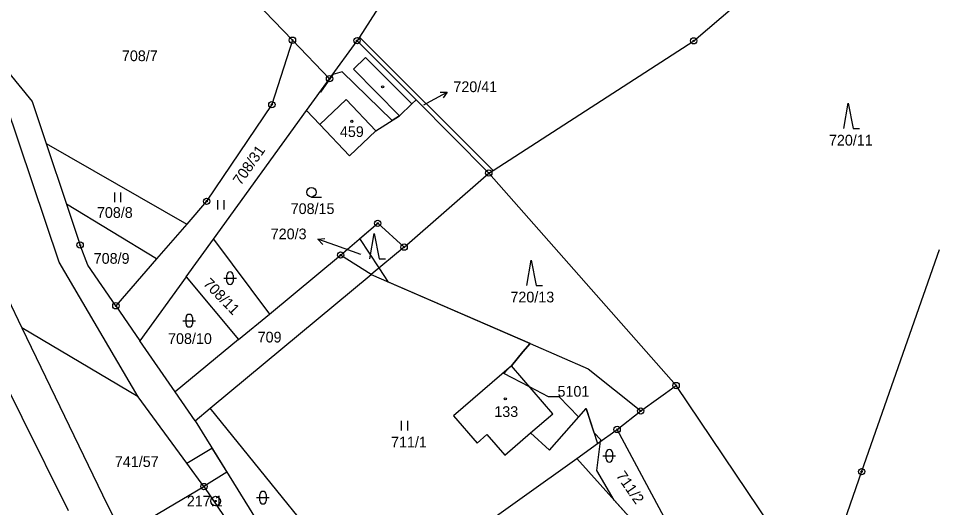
# Model space of a CAD drawing. Extents: x -439246 to -433691, y -1130252 to -1121148.
# Drawn here: x -436950.7 to -436805.1, y -1125491.1 to -1125413.5 of the extents above; entities that cross this region are included whole.
import ezdxf

# ---------------------------------------------------------------- set-up
doc = ezdxf.new("R2010")
doc.units = 0
for name, color, linetype in [('Vrstva 1', 7, 'Continuous'), ('Vrstva 16', 7, 'Continuous'), ('Vrstva 17', 7, 'Continuous'), ('Vrstva 18', 7, 'Continuous'), ('Vrstva 19', 7, 'Continuous'), ('Vrstva 24', 7, 'Continuous'), ('Vrstva 25', 7, 'Continuous'), ('Vrstva 3', 7, 'Continuous'), ('Vrstva 30', 7, 'Continuous'), ('Vrstva 37', 7, 'Continuous'), ('Vrstva 4', 7, 'Continuous'), ('Vrstva 52', 7, 'Continuous'), ('Vrstva 6', 7, 'Continuous')]:
    doc.layers.add(name, color=color, linetype=linetype)

msp = doc.modelspace()

# ---------------------------------------------------------------- linework, layer by layer
at = {"layer": 'Vrstva 1'}
for points in [[(-436927.94, -1125395.35), (-436907.12, -1125416.96)], [(-436843.38, -1125417.06), (-436817.3, -1125394.78)], [(-436887.02, -1125401.73), (-436896.49, -1125416.46)], [(-436965.4, -1125405.95), (-436948.45, -1125426.71)], [(-436907.12, -1125416.96), (-436910.39, -1125427.18), (-436920.75, -1125442.51)], [(-436907.12, -1125416.96), (-436901.23, -1125423.07)], [(-436901.23, -1125423.07), (-436896.86, -1125417.04)], [(-436896.49, -1125416.46), (-436896.86, -1125417.04)], [(-436896.86, -1125417.04), (-436887.49, -1125426.4)], [(-436875.23, -1125437.61), (-436843.38, -1125417.06)], [(-436904.89, -1125428.12), (-436901.23, -1125423.07)], [(-436888.17, -1125427.07), (-436887.49, -1125426.4)], [(-436887.49, -1125426.4), (-436875.93, -1125438.04)], [(-436944.18, -1125452.16), (-436952.63, -1125426.98)], [(-436948.45, -1125426.71), (-436946.24, -1125433.35)], [(-436888.17, -1125427.07), (-436890.09, -1125428.97)], [(-436919.68, -1125448.54), (-436904.89, -1125428.12)], [(-436902.75, -1125430.36), (-436904.89, -1125428.12)], [(-436893.88, -1125431.32), (-436890.09, -1125428.97)], [(-436902.75, -1125430.36), (-436898.04, -1125435.29)], [(-436898.04, -1125435.29), (-436893.88, -1125431.32)], [(-436946.24, -1125433.35), (-436923.9, -1125446.13)], [(-436946.24, -1125433.35), (-436943.03, -1125442.95)], [(-436889.38, -1125449.79), (-436875.93, -1125438.04)], [(-436875.93, -1125438.04), (-436875.23, -1125437.61)], [(-436846.17, -1125471.75), (-436875.93, -1125438.04)], [(-436928.71, -1125451.67), (-436943.03, -1125442.95)], [(-436943.03, -1125442.95), (-436940.85, -1125449.46)], [(-436920.75, -1125442.51), (-436923.9, -1125446.13)], [(-436923.9, -1125446.13), (-436928.71, -1125451.67)], [(-436899.47, -1125451.05), (-436893.57, -1125446.01)], [(-436893.57, -1125446.01), (-436889.38, -1125449.79)], [(-436939.63, -1125452.63), (-436940.85, -1125449.46)], [(-436924.02, -1125454.53), (-436919.68, -1125448.54)], [(-436919.68, -1125448.54), (-436910.79, -1125460.41)], [(-436910.79, -1125460.41), (-436899.47, -1125451.05)], [(-436894.61, -1125454.14), (-436899.47, -1125451.05)], [(-436889.38, -1125449.79), (-436894.61, -1125454.14)], [(-436804.38, -1125450.21), (-436816.7, -1125485.41)], [(-436931.61, -1125473.53), (-436944.18, -1125452.16)], [(-436935.17, -1125459.1), (-436939.63, -1125452.63)], [(-436928.71, -1125451.67), (-436935.17, -1125459.1)], [(-436924.02, -1125454.53), (-436931.35, -1125464.65)], [(-436924.02, -1125454.53), (-436915.7, -1125464.46)], [(-436920.18, -1125475.35), (-436894.61, -1125454.14)], [(-436894.61, -1125454.14), (-436869.38, -1125465.08)], [(-436952.37, -1125457.85), (-436950.1, -1125462.57)], [(-436935.17, -1125459.1), (-436931.35, -1125464.65)], [(-436915.7, -1125464.46), (-436910.79, -1125460.41)], [(-436942.68, -1125491.62), (-436957.49, -1125462.02)], [(-436931.61, -1125473.53), (-436950.1, -1125462.57)], [(-436950.1, -1125462.57), (-436936.58, -1125490.62)], [(-436925.75, -1125472.77), (-436931.35, -1125464.65)], [(-436915.7, -1125464.46), (-436925.75, -1125472.77)], [(-436869.38, -1125465.08), (-436870.54, -1125466.41), (-436872.33, -1125468.61)], [(-436869.38, -1125465.08), (-436860.12, -1125469.1)], [(-436872.33, -1125468.61), (-436881.53, -1125476.54), (-436877.79, -1125480.87), (-436876.22, -1125479.51), (-436873.36, -1125482.79), (-436869.29, -1125479.28)], [(-436869.29, -1125479.28), (-436865.78, -1125476.26), (-436872.33, -1125468.61)], [(-436860.12, -1125469.1), (-436851.79, -1125475.78)], [(-436922.59, -1125477.35), (-436925.75, -1125472.77)], [(-436851.79, -1125475.78), (-436846.17, -1125471.75)], [(-436823.62, -1125505.2), (-436846.17, -1125471.75)], [(-436923.89, -1125484.05), (-436931.61, -1125473.53)], [(-436922.59, -1125477.35), (-436920.18, -1125475.35)], [(-436894.71, -1125506.76), (-436920.18, -1125475.35)], [(-436866.29, -1125481.99), (-436860.48, -1125475.37)], [(-436860.48, -1125475.37), (-436858.64, -1125480.94)], [(-436855.54, -1125478.72), (-436851.79, -1125475.78)], [(-436922.59, -1125477.35), (-436901.39, -1125511.56)], [(-436858.64, -1125480.94), (-436855.54, -1125478.72)], [(-436844.53, -1125499.26), (-436855.54, -1125478.72)], [(-436866.29, -1125481.99), (-436869.29, -1125479.28)], [(-436861.96, -1125483.32), (-436858.64, -1125480.94)], [(-436921.18, -1125487.78), (-436923.89, -1125484.05)], [(-436878.93, -1125495.46), (-436861.96, -1125483.32)], [(-436846.62, -1125500.38), (-436861.96, -1125483.32)], [(-436816.7, -1125485.41), (-436823.62, -1125505.2)], [(-436933.11, -1125494.8), (-436921.18, -1125487.78)], [(-436921.18, -1125487.78), (-436906.49, -1125509.43)], [(-436936.58, -1125490.62), (-436934.13, -1125495.4)]]:
    msp.add_lwpolyline(points, dxfattribs=at)
at = {"layer": 'Vrstva 16'}
for p, q in [((-436885.18, -1125426.63), (-436882.55, -1125425.19)), ((-436900.24, -1125449.55), (-436903.07, -1125448.55))]:
    msp.add_line(p, q, dxfattribs=at)
for points in [[(-436883.66, -1125425.23), (-436882.55, -1125425.19), (-436883.18, -1125426.11)], [(-436886.24, -1125427.21), (-436885.18, -1125426.63)], [(-436902.29, -1125449.35), (-436903.07, -1125448.55), (-436901.96, -1125448.41)], [(-436896.28, -1125450.96), (-436900.24, -1125449.55)]]:
    msp.add_lwpolyline(points, dxfattribs=at)
at = {"layer": 'Vrstva 24'}
for centre, radius in [((-436907.12, -1125416.96), 0.5), ((-436907.12, -1125416.96), 0.1), ((-436896.86, -1125417.04), 0.5), ((-436896.86, -1125417.04), 0.1), ((-436843.38, -1125417.06), 0.5), ((-436843.38, -1125417.06), 0.1), ((-436901.23, -1125423.07), 0.5), ((-436901.23, -1125423.07), 0.1), ((-436910.39, -1125427.18), 0.5), ((-436910.39, -1125427.18), 0.1), ((-436875.93, -1125438.04), 0.5), ((-436875.93, -1125438.04), 0.1), ((-436920.75, -1125442.51), 0.5), ((-436920.75, -1125442.51), 0.1), ((-436893.57, -1125446.01), 0.5), ((-436893.57, -1125446.01), 0.1), ((-436940.85, -1125449.46), 0.5), ((-436940.85, -1125449.46), 0.1), ((-436889.38, -1125449.79), 0.5), ((-436889.38, -1125449.79), 0.1), ((-436899.47, -1125451.05), 0.5), ((-436899.47, -1125451.05), 0.1), ((-436935.17, -1125459.1), 0.5), ((-436935.17, -1125459.1), 0.1), ((-436846.17, -1125471.75), 0.5), ((-436846.17, -1125471.75), 0.1), ((-436851.79, -1125475.78), 0.5), ((-436851.79, -1125475.78), 0.1), ((-436855.54, -1125478.72), 0.5), ((-436855.54, -1125478.72), 0.1), ((-436816.7, -1125485.41), 0.5), ((-436816.7, -1125485.41), 0.1), ((-436921.18, -1125487.78), 0.5), ((-436921.18, -1125487.78), 0.1), ((-436919.32, -1125490.08), 0.75), ((-436919.32, -1125490.08), 0.1)]:
    msp.add_circle(centre, radius, dxfattribs=at)
at = {"layer": 'Vrstva 25'}
for p, q in [((-436935.36, -1125442.64), (-436935.36, -1125441.14)), ((-436934.36, -1125442.64), (-436934.36, -1125441.14)), ((-436918.95, -1125443.82), (-436918.95, -1125442.32)), ((-436917.95, -1125443.82), (-436917.95, -1125442.32)), ((-436904.1, -1125441.84), (-436902.5, -1125441.84)), ((-436918.03, -1125454.73), (-436916.03, -1125454.73)), ((-436917.53, -1125455.23), (-436917.53, -1125454.23)), ((-436916.53, -1125454.23), (-436916.53, -1125455.23)), ((-436924.02, -1125461.96), (-436924.02, -1125460.96)), ((-436923.02, -1125460.96), (-436923.02, -1125461.96)), ((-436924.52, -1125461.46), (-436922.52, -1125461.46)), ((-436889.78, -1125478.87), (-436889.78, -1125477.37)), ((-436888.78, -1125478.87), (-436888.78, -1125477.37)), ((-436857.79, -1125482.9), (-436855.79, -1125482.9)), ((-436857.29, -1125483.4), (-436857.29, -1125482.4)), ((-436856.29, -1125482.4), (-436856.29, -1125483.4)), ((-436912.31, -1125490.04), (-436912.31, -1125489.04)), ((-436911.31, -1125489.04), (-436911.31, -1125490.04)), ((-436912.81, -1125489.54), (-436910.81, -1125489.54))]:
    msp.add_line(p, q, dxfattribs=at)
for points in [[(-436819.52, -1125430.97), (-436818.82, -1125426.97), (-436818.02, -1125430.97), (-436817.02, -1125430.97)], [(-436894.83, -1125451.65), (-436894.13, -1125447.65), (-436893.33, -1125451.65), (-436892.33, -1125451.65)], [(-436869.9, -1125455.86), (-436869.2, -1125451.86), (-436868.4, -1125455.86), (-436867.4, -1125455.86)]]:
    msp.add_lwpolyline(points, dxfattribs=at)
for centre, radius in [((-436892.8, -1125424.36), 0.175), ((-436897.69, -1125429.83), 0.175), ((-436904.1, -1125441.09), 0.75), ((-436873.31, -1125473.86), 0.175)]:
    msp.add_circle(centre, radius, dxfattribs=at)
for centre, start, end in [((-436917.03, -1125454.23), 0, 180), ((-436917.03, -1125455.23), 180, 0), ((-436923.52, -1125460.96), 0, 180), ((-436923.52, -1125461.96), 180, 0), ((-436856.79, -1125482.4), 0, 180), ((-436856.79, -1125483.4), 180, 0), ((-436911.81, -1125489.04), 0, 180), ((-436911.81, -1125490.04), 180, 0)]:
    msp.add_arc(centre, 0.5, start, end, dxfattribs=at)
at = {"layer": 'Vrstva 3'}
for points in [[(-436902.75, -1125430.36), (-436898.59, -1125426.39)], [(-436898.59, -1125426.39), (-436893.88, -1125431.32)], [(-436902.75, -1125430.36), (-436898.04, -1125435.29)], [(-436898.04, -1125435.29), (-436893.88, -1125431.32)], [(-436872.33, -1125468.61), (-436881.53, -1125476.54), (-436877.79, -1125480.87), (-436876.22, -1125479.51), (-436873.36, -1125482.79), (-436869.29, -1125479.28)], [(-436869.29, -1125479.28), (-436865.78, -1125476.26), (-436872.33, -1125468.61)]]:
    msp.add_lwpolyline(points, dxfattribs=at)
at = {"layer": 'Vrstva 30'}
msp.add_lwpolyline([(-436923.89, -1125484.05), (-436919.91, -1125481.68), (-436917.53, -1125485.51), (-436921.18, -1125487.78), (-436923.89, -1125484.05)], dxfattribs=at)
at = {"layer": 'Vrstva 37'}
for centre in [(-436897.69, -1125429.83), (-436873.31, -1125473.86)]:
    msp.add_circle(centre, 0.175, dxfattribs=at)
at = {"layer": 'Vrstva 4'}
for points in [[(-436895.49, -1125419.68), (-436897.4, -1125421.58)], [(-436895.49, -1125419.68), (-436888.17, -1125427.07)], [(-436897.4, -1125421.58), (-436890.09, -1125428.97)], [(-436902.75, -1125430.36), (-436898.59, -1125426.39)], [(-436898.59, -1125426.39), (-436893.88, -1125431.32)]]:
    msp.add_lwpolyline(points, dxfattribs=at)
at = {"layer": 'Vrstva 52'}
msp.add_lwpolyline([(-436846.62, -1125500.38), (-436856.02, -1125489.92), (-436858.76, -1125485.25), (-436858.38, -1125482.29), (-436858.16, -1125480.6), (-436858.12, -1125480.35), (-436859.2, -1125479.24), (-436860.48, -1125475.37), (-436861.66, -1125476.71), (-436864.73, -1125473.54), (-436866.43, -1125473.54), (-436869.47, -1125471.95), (-436873.53, -1125469.83), (-436872.87, -1125469.08), (-436872.33, -1125468.61), (-436870.54, -1125466.41), (-436869.38, -1125465.08), (-436891.86, -1125455.33), (-436893.34, -1125453.08), (-436896.39, -1125448.42), (-436893.57, -1125446.01), (-436889.38, -1125449.79), (-436875.93, -1125438.04), (-436887.49, -1125426.4), (-436888.17, -1125427.07), (-436890.09, -1125428.97), (-436891.28, -1125429.71), (-436899.24, -1125421.98), (-436900.73, -1125422.41), (-436902.65, -1125425.18), (-436902.78, -1125425.21), (-436901.23, -1125423.07), (-436907.12, -1125416.96), (-436927.94, -1125395.35)], dxfattribs=at)
at = {"layer": 'Vrstva 6'}
msp.add_lwpolyline([(-436875.23, -1125437.61), (-436896.49, -1125416.46)], dxfattribs=at)

# ---------------------------------------------------------------- texts
at = {"layer": 'Vrstva 16'}
for s, p in [('720/41', (-436881.55, -1125425.19)), ('720/3', (-436910.57, -1125448.55))]:
    msp.add_text(s, height=1.7, dxfattribs=at).set_placement(p)
at = {"layer": 'Vrstva 17'}
msp.add_text('217.1', height=1.7, dxfattribs=at).set_placement((-436923.9, -1125490.93))
at = {"layer": 'Vrstva 18'}
for s, height, p in [('708/7', 1.7, (-436934.21, -1125420.28)), ('720/41', 0.1, (-436886.45, -1125427.21)), ('720/11', 1.7, (-436821.89, -1125433.67)), ('708/8', 1.7, (-436938.18, -1125445.15)), ('708/15', 1.7, (-436907.4, -1125444.54)), ('708/9', 1.7, (-436938.69, -1125452.43)), ('720/3', 0.1, (-436896.47, -1125450.96)), ('720/13', 1.7, (-436872.49, -1125458.56)), ('708/10', 1.7, (-436926.88, -1125465.16)), ('709', 1.7, (-436912.65, -1125464.92)), ('5101', 1.7, (-436865.01, -1125473.52)), ('711/1', 1.7, (-436891.46, -1125481.57)), ('741/57', 1.7, (-436935.33, -1125484.68))]:
    msp.add_text(s, height=height, dxfattribs=at).set_placement(p)
for s, rotation, p in [('708/31', 55.1759, (-436915.33, -1125440.11)), ('708/11', 314.138, (-436921.41, -1125455.69)), ('711/2', 304.7763, (-436855.78, -1125486.06))]:
    msp.add_text(s, height=1.7, rotation=rotation, dxfattribs=at).set_placement(p)
at = {"layer": 'Vrstva 19'}
for s, p in [('459', (-436899.58, -1125432.32)), ('133', (-436875.05, -1125476.74))]:
    msp.add_text(s, height=1.7, dxfattribs=at).set_placement(p)

doc.saveas('drawing.dxf')
